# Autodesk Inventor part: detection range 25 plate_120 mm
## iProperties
Shininess: 20.0
Length Units: 11269
Angle Units: 11279
Time Units: 11290
Mass Units: 11283
Length Display Precision: 3
Angle Display Precision: 2
Part Number: detection range 25 plate_120 mm
Material: Lexan (klar)
Document SubType Name: Modellieren
Description: Schallfeld 0,25 m
Checked By: Alves
Created: 2005-08
Designer: Klein
Manufacturer: Standard
Standards Organization: Custom
Density: 0.0
Volumn: 0.0
Area: 0.0
PropertySet Name: Model Information
Control State: 0
Master: False
Checked Out: False
BESTELLNUMMER: 0,25 m
ME: ST
Title: Schallfelder
Author: Klein
Comments: keine Bemerkung
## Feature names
1. Blindzone_Aussenglocke [Revolution]
2. Umdrehung5 [Revolution]
